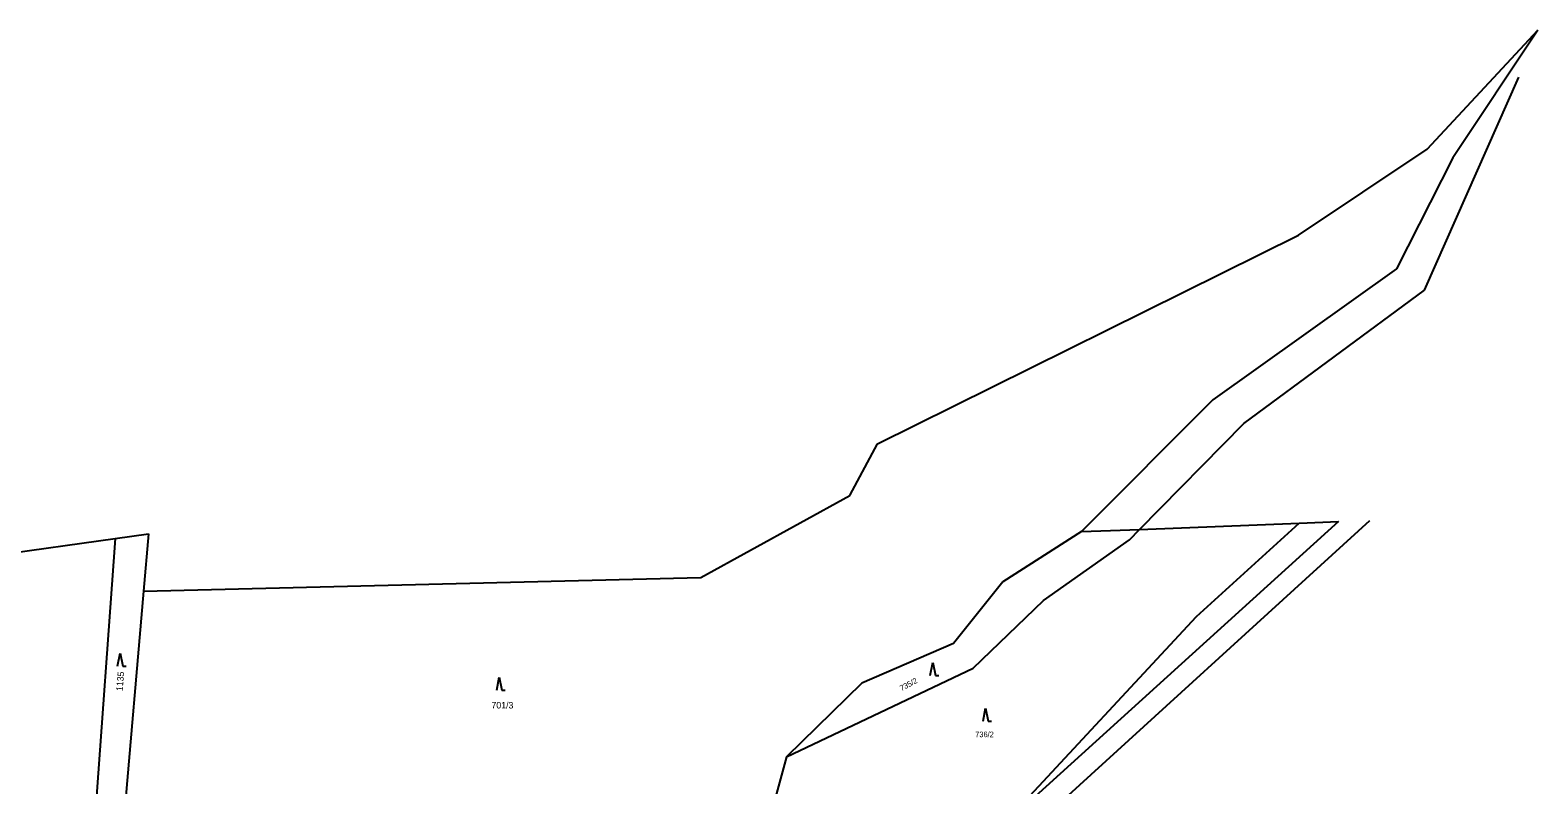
# Model space of a CAD drawing. Extents: x -553108 to -552267, y -1076883 to -1076631.
# Drawn here: x -552955.1 to -552724.8, y -1076746.6 to -1076631.4 of the extents above; entities that cross this region are included whole.
import ezdxf

# ---------------------------------------------------------------- set-up
doc = ezdxf.new("R2010")
doc.units = 0
doc.layers.add('Vrstva 46', color=7, linetype='Continuous')
doc.layers.add('Vrstva 53', color=7, linetype='Continuous')

msp = doc.modelspace()

# ---------------------------------------------------------------- linework, layer by layer
at = {"layer": 'Vrstva 46'}
for p, q in [((-552741.74, -1076649.53), (-552724.82, -1076631.37)), ((-552724.82, -1076631.37), (-552737.8, -1076650.84)), ((-552742.14, -1076671.04), (-552727.74, -1076638.55)), ((-552761.39, -1076662.66), (-552741.74, -1076649.53)), ((-552737.8, -1076650.84), (-552746.41, -1076667.81)), ((-552825.68, -1076694.53), (-552761.39, -1076662.66)), ((-552746.41, -1076667.81), (-552774.47, -1076687.77)), ((-552769.75, -1076691.41), (-552742.14, -1076671.04)), ((-552774.47, -1076687.77), (-552794.51, -1076707.91)), ((-552785.65, -1076707.57), (-552769.75, -1076691.41)), ((-552829.92, -1076702.39), (-552825.68, -1076694.53)), ((-552852.69, -1076714.91), (-552829.92, -1076702.39)), ((-552755.28, -1076706.38), (-552807.25, -1076753.41)), ((-552802.53, -1076753.57), (-552750.48, -1076706.2)), ((-552761.3, -1076706.62), (-552755.28, -1076706.38)), ((-552942.15, -1076708.95), (-552937.05, -1076708.24)), ((-552937.05, -1076708.24), (-552937.81, -1076716.99)), ((-552794.51, -1076707.91), (-552806.55, -1076715.56)), ((-552794.51, -1076707.91), (-552785.65, -1076707.57)), ((-552787.22, -1076709.16), (-552785.65, -1076707.57)), ((-552785.65, -1076707.57), (-552761.3, -1076706.62)), ((-552776.98, -1076720.85), (-552761.3, -1076706.62)), ((-552975.92, -1076713.65), (-552942.15, -1076708.95)), ((-552942.15, -1076708.95), (-552945.41, -1076753.61)), ((-552800.36, -1076718.42), (-552787.22, -1076709.16)), ((-552937.81, -1076716.99), (-552852.69, -1076714.91)), ((-552806.55, -1076715.56), (-552814.09, -1076724.99)), ((-552937.81, -1076716.99), (-552941, -1076753.93)), ((-552811.06, -1076728.76), (-552800.36, -1076718.42)), ((-552807.25, -1076753.41), (-552776.98, -1076720.85)), ((-552814.09, -1076724.99), (-552828.07, -1076731.05)), ((-552839.59, -1076742.27), (-552811.06, -1076728.76)), ((-552828.07, -1076731.05), (-552839.59, -1076742.27)), ((-552839.59, -1076742.27), (-552842.7, -1076753.67))]:
    msp.add_line(p, q, dxfattribs=at)
at = {"layer": 'Vrstva 53'}
for p, q in [((-552941.79, -1076728.44), (-552941.39, -1076726.44)), ((-552941.39, -1076726.44), (-552940.99, -1076728.44)), ((-552940.99, -1076728.44), (-552940.49, -1076728.44)), ((-552817.63, -1076729.89), (-552817.23, -1076727.89)), ((-552817.23, -1076727.89), (-552816.83, -1076729.89)), ((-552883.87, -1076732.1), (-552883.47, -1076730.1)), ((-552883.47, -1076730.1), (-552883.07, -1076732.1)), ((-552816.83, -1076729.89), (-552816.33, -1076729.89)), ((-552883.07, -1076732.1), (-552882.57, -1076732.1)), ((-552809.58, -1076736.84), (-552809.18, -1076734.84)), ((-552809.18, -1076734.84), (-552808.78, -1076736.84)), ((-552808.78, -1076736.84), (-552808.28, -1076736.84))]:
    msp.add_line(p, q, dxfattribs=at)

# ---------------------------------------------------------------- texts
for s, height, rotation, p in [('1135', 1, 85.0644, (-552941.02, -1076732.28)), ('735/2', 0.85, 27.9075, (-552822.02, -1076732.26))]:
    msp.add_text(s, height=height, rotation=rotation, dxfattribs=at).set_placement(p)
for s, height, p in [('701/3', 1, (-552884.67, -1076734.9)), ('736/2', 0.85, (-552810.77, -1076739.28))]:
    msp.add_text(s, height=height, dxfattribs=at).set_placement(p)

doc.saveas('drawing.dxf')
